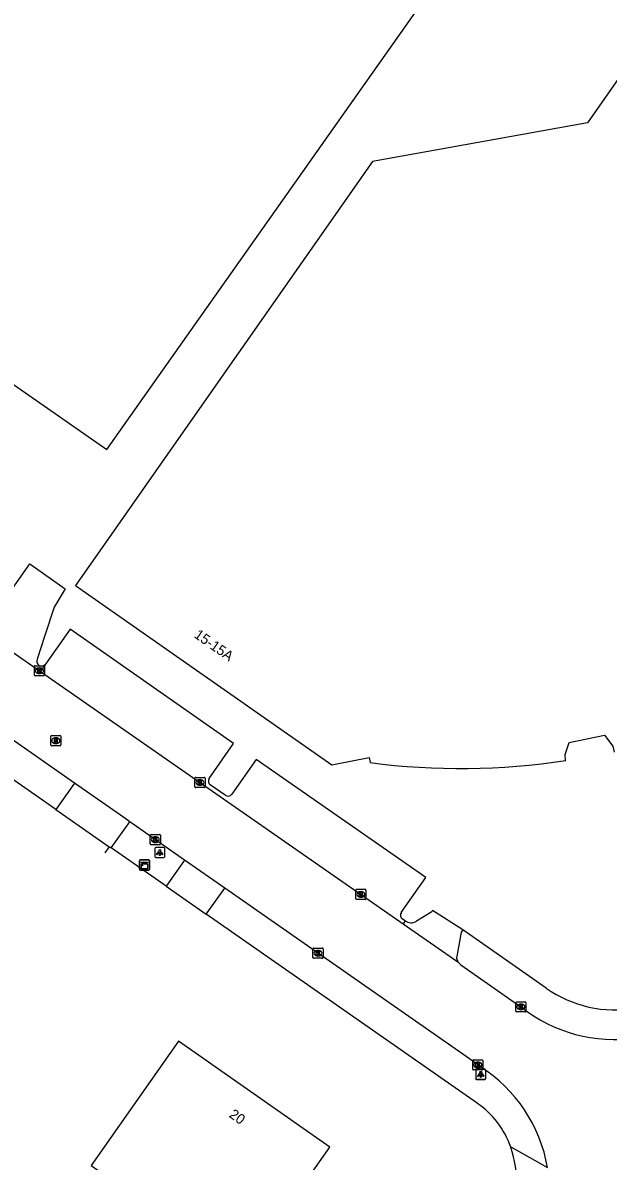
# Model space of a CAD drawing. Extents: x 155018 to 156648, y 383980 to 385733.
# Drawn here: x 155376.9 to 155434.7, y 385021.9 to 385134.4 of the extents above; entities that cross this region are included whole.
import ezdxf

# ---------------------------------------------------------------- set-up
doc = ezdxf.new("R2010")
doc.units = 0
for name, color, linetype in [('IMGEO_Hek', 7, 'Continuous'), ('IMGEO_Kast', 7, 'Continuous'), ('IMGEO_Kolk', 7, 'Continuous'), ('IMGEO_Lichtpunt', 7, 'Continuous'), ('IMGEO_Pand', 7, 'Continuous'), ('IMGEO_Pand_nummerreeks', 7, 'Continuous'), ('IMGEO_Parkeervlak_open', 7, 'Continuous'), ('IMGEO_Rijbaan_lokaal_gesloten', 7, 'Continuous'), ('IMGEO_Rijbaan_lokaal_open', 7, 'Continuous'), ('IMGEO_Rioolput', 7, 'Continuous'), ('IMGEO_Voetpad_open', 7, 'Continuous')]:
    doc.layers.add(name, color=color, linetype=linetype)

msp = doc.modelspace()

# ---------------------------------------------------------------- linework, layer by layer
at = {"layer": 'IMGEO_Hek'}
msp.add_lwpolyline([(155385.4, 385052.96), (155384.98, 385052.36)], dxfattribs=at)
at = {"layer": 'IMGEO_Kast'}
for p, q in [((155388.4, 385050.73), (155388.4, 385051.57)), ((155388.4, 385051.57), (155388.4, 385050.73)), ((155388.47, 385051.65), (155389.31, 385051.65)), ((155389.31, 385051.65), (155388.47, 385051.65)), ((155389.39, 385051.58), (155389.39, 385050.74)), ((155389.39, 385050.74), (155389.39, 385051.58)), ((155389.32, 385050.65), (155388.48, 385050.65)), ((155388.48, 385050.65), (155389.32, 385050.65))]:
    msp.add_line(p, q, dxfattribs=at)
for points in [[(155388.59, 385051.44), (155389.19, 385051.44), (155389.19, 385051.36), (155388.59, 385051.36), (155388.59, 385051.44)], [(155388.59, 385051.27), (155389.19, 385051.27), (155389.19, 385050.78), (155388.59, 385050.78), (155388.59, 385051.27)]]:
    msp.add_lwpolyline(points, dxfattribs=at)
msp.add_circle((155388.67, 385051.12), 0.0377, dxfattribs=at)
for centre, start, end in [((155388.47, 385051.57), 92.4484, 184.2845), ((155388.47, 385051.57), 92.4484, 184.2845), ((155389.32, 385051.57), 2.4484, 94.2845), ((155389.32, 385051.57), 2.4484, 94.2845), ((155388.47, 385050.73), 182.4484, 274.2845), ((155388.47, 385050.73), 182.4484, 274.2845), ((155389.32, 385050.73), 272.4484, 4.2845), ((155389.32, 385050.73), 272.4484, 4.2845)]:
    msp.add_arc(centre, 0.0779, start, end, dxfattribs=at)
at = {"layer": 'IMGEO_Kolk'}
for p, q in [((155378.02, 385069.92), (155378.02, 385070.77)), ((155378.09, 385070.85), (155378.94, 385070.85)), ((155378.53, 385070.07), (155378.5, 385070.07)), ((155378.51, 385070.63), (155378.53, 385070.63)), ((155379.02, 385070.77), (155379.02, 385069.92)), ((155378.94, 385069.85), (155378.09, 385069.85)), ((155393.96, 385059.81), (155394.81, 385059.81)), ((155393.88, 385058.88), (155393.88, 385059.73)), ((155394.81, 385058.81), (155393.96, 385058.81)), ((155394.37, 385059.59), (155394.4, 385059.59)), ((155394.39, 385059.03), (155394.37, 385059.03)), ((155394.88, 385059.73), (155394.88, 385058.88)), ((155389.54, 385054.16), (155390.39, 385054.16)), ((155389.46, 385053.24), (155389.46, 385054.09)), ((155390.39, 385053.16), (155389.54, 385053.16)), ((155389.95, 385053.94), (155389.98, 385053.94)), ((155389.97, 385053.38), (155389.95, 385053.38)), ((155390.46, 385054.09), (155390.46, 385053.24)), ((155409.78, 385047.82), (155409.78, 385048.67)), ((155409.85, 385048.75), (155410.71, 385048.75)), ((155410.27, 385048.52), (155410.29, 385048.52)), ((155410.78, 385048.67), (155410.78, 385047.82)), ((155410.71, 385047.74), (155409.85, 385047.74)), ((155410.29, 385047.97), (155410.26, 385047.97)), ((155405.61, 385042.93), (155406.46, 385042.93)), ((155405.53, 385042.01), (155405.53, 385042.86)), ((155406.46, 385041.93), (155405.61, 385041.93)), ((155406.02, 385042.71), (155406.05, 385042.71)), ((155406.04, 385042.15), (155406.02, 385042.15)), ((155406.54, 385042.86), (155406.54, 385042.01)), ((155425.59, 385036.7), (155425.59, 385037.55)), ((155425.66, 385037.63), (155426.51, 385037.63)), ((155426.08, 385037.41), (155426.1, 385037.41)), ((155426.59, 385037.55), (155426.59, 385036.7)), ((155426.51, 385036.63), (155425.66, 385036.63)), ((155426.1, 385036.85), (155426.07, 385036.85)), ((155421.33, 385030.97), (155421.33, 385031.82)), ((155421.4, 385031.89), (155422.26, 385031.89)), ((155421.82, 385031.67), (155421.84, 385031.67)), ((155422.33, 385031.82), (155422.33, 385030.97)), ((155422.26, 385030.89), (155421.4, 385030.89)), ((155421.84, 385031.11), (155421.81, 385031.11))]:
    msp.add_line(p, q, dxfattribs=at)
for points in [[(155378.02, 385069.92), (155378.02, 385070.77)], [(155378.09, 385070.85), (155378.94, 385070.85)], [(155378.34, 385070.55), (155378.46, 385070.55), (155378.46, 385070.39), (155378.59, 385070.55), (155378.76, 385070.55), (155378.61, 385070.4), (155378.76, 385070.15), (155378.61, 385070.15), (155378.53, 385070.31), (155378.46, 385070.24), (155378.46, 385070.15), (155378.34, 385070.15), (155378.34, 385070.55)], [(155379.02, 385070.77), (155379.02, 385069.92)], [(155378.94, 385069.85), (155378.09, 385069.85)], [(155393.96, 385059.81), (155394.81, 385059.81)], [(155393.88, 385058.88), (155393.88, 385059.73)], [(155394.81, 385058.81), (155393.96, 385058.81)], [(155394.2, 385059.51), (155394.33, 385059.51), (155394.33, 385059.36), (155394.46, 385059.51), (155394.62, 385059.51), (155394.47, 385059.36), (155394.63, 385059.11), (155394.47, 385059.11), (155394.39, 385059.27), (155394.33, 385059.2), (155394.33, 385059.11), (155394.2, 385059.11), (155394.2, 385059.51)], [(155394.88, 385059.73), (155394.88, 385058.88)], [(155389.54, 385054.16), (155390.39, 385054.16)], [(155389.46, 385053.24), (155389.46, 385054.09)], [(155390.39, 385053.16), (155389.54, 385053.16)], [(155389.78, 385053.86), (155389.91, 385053.86), (155389.91, 385053.71), (155390.04, 385053.86), (155390.2, 385053.86), (155390.05, 385053.71), (155390.21, 385053.46), (155390.05, 385053.46), (155389.97, 385053.63), (155389.91, 385053.56), (155389.91, 385053.46), (155389.78, 385053.46), (155389.78, 385053.86)], [(155390.46, 385054.09), (155390.46, 385053.24)], [(155409.78, 385047.82), (155409.78, 385048.67)], [(155409.85, 385048.75), (155410.71, 385048.75)], [(155410.78, 385048.67), (155410.78, 385047.82)], [(155410.71, 385047.74), (155409.85, 385047.74)], [(155410.1, 385048.44), (155410.22, 385048.44), (155410.22, 385048.29), (155410.35, 385048.44), (155410.52, 385048.44), (155410.37, 385048.29), (155410.52, 385048.04), (155410.37, 385048.04), (155410.29, 385048.21), (155410.22, 385048.14), (155410.22, 385048.04), (155410.1, 385048.04), (155410.1, 385048.44)], [(155405.61, 385042.93), (155406.46, 385042.93)], [(155405.53, 385042.01), (155405.53, 385042.86)], [(155406.46, 385041.93), (155405.61, 385041.93)], [(155405.85, 385042.63), (155405.98, 385042.63), (155405.98, 385042.48), (155406.11, 385042.63), (155406.27, 385042.63), (155406.13, 385042.48), (155406.28, 385042.23), (155406.13, 385042.23), (155406.04, 385042.4), (155405.98, 385042.33), (155405.98, 385042.23), (155405.85, 385042.23), (155405.85, 385042.63)], [(155406.54, 385042.86), (155406.54, 385042.01)], [(155425.59, 385036.7), (155425.59, 385037.55)], [(155425.66, 385037.63), (155426.51, 385037.63)], [(155425.91, 385037.33), (155426.03, 385037.33), (155426.03, 385037.18), (155426.16, 385037.33), (155426.33, 385037.33), (155426.18, 385037.18), (155426.33, 385036.93), (155426.18, 385036.93), (155426.1, 385037.09), (155426.03, 385037.02), (155426.03, 385036.93), (155425.91, 385036.93), (155425.91, 385037.33)], [(155426.59, 385037.55), (155426.59, 385036.7)], [(155426.51, 385036.63), (155425.66, 385036.63)], [(155421.33, 385030.97), (155421.33, 385031.82)], [(155421.4, 385031.89), (155422.26, 385031.89)], [(155422.33, 385031.82), (155422.33, 385030.97)], [(155422.26, 385030.89), (155421.4, 385030.89)], [(155421.65, 385031.59), (155421.77, 385031.59), (155421.77, 385031.44), (155421.9, 385031.59), (155422.07, 385031.59), (155421.92, 385031.44), (155422.07, 385031.19), (155421.92, 385031.19), (155421.84, 385031.36), (155421.77, 385031.29), (155421.77, 385031.19), (155421.65, 385031.19), (155421.65, 385031.59)]]:
    msp.add_lwpolyline(points, dxfattribs=at)
for centre, start, end in [((155378.09, 385070.77), 91.552, 178.448), ((155378.09, 385070.77), 91.552, 178.448), ((155378.09, 385069.92), 181.552, 268.448), ((155378.09, 385069.92), 181.552, 268.448), ((155378.94, 385070.77), 1.552, 88.448), ((155378.94, 385070.77), 1.552, 88.448), ((155378.94, 385069.92), 271.552, 358.448), ((155378.94, 385069.92), 271.552, 358.448), ((155393.96, 385059.73), 91.552, 178.448), ((155393.96, 385059.73), 91.552, 178.448), ((155394.81, 385059.73), 1.552, 88.448), ((155394.81, 385059.73), 1.552, 88.448), ((155393.96, 385058.88), 181.552, 268.448), ((155393.96, 385058.88), 181.552, 268.448), ((155394.81, 385058.88), 271.552, 358.448), ((155394.81, 385058.88), 271.552, 358.448), ((155389.54, 385054.09), 91.552, 178.448), ((155389.54, 385054.09), 91.552, 178.448), ((155390.39, 385054.09), 1.552, 88.448), ((155390.39, 385054.09), 1.552, 88.448), ((155389.54, 385053.24), 181.552, 268.448), ((155389.54, 385053.24), 181.552, 268.448), ((155390.39, 385053.24), 271.552, 358.448), ((155390.39, 385053.24), 271.552, 358.448), ((155409.86, 385048.67), 91.552, 178.448), ((155409.86, 385048.67), 91.552, 178.448), ((155410.7, 385048.67), 1.552, 88.448), ((155410.7, 385048.67), 1.552, 88.448), ((155409.86, 385047.82), 181.552, 268.448), ((155409.86, 385047.82), 181.552, 268.448), ((155410.7, 385047.82), 271.552, 358.448), ((155410.7, 385047.82), 271.552, 358.448), ((155405.61, 385042.86), 91.552, 178.448), ((155405.61, 385042.86), 91.552, 178.448), ((155406.46, 385042.86), 1.552, 88.448), ((155406.46, 385042.86), 1.552, 88.448), ((155405.61, 385042.01), 181.552, 268.448), ((155405.61, 385042.01), 181.552, 268.448), ((155406.46, 385042.01), 271.552, 358.448), ((155406.46, 385042.01), 271.552, 358.448), ((155425.66, 385037.55), 91.552, 178.448), ((155425.66, 385037.55), 91.552, 178.448), ((155426.51, 385037.55), 1.552, 88.448), ((155426.51, 385037.55), 1.552, 88.448), ((155425.66, 385036.7), 181.552, 268.448), ((155425.66, 385036.7), 181.552, 268.448), ((155426.51, 385036.7), 271.552, 358.448), ((155426.51, 385036.7), 271.552, 358.448), ((155421.4, 385031.82), 91.552, 178.448), ((155421.4, 385031.82), 91.552, 178.448), ((155422.25, 385031.82), 1.552, 88.448), ((155422.25, 385031.82), 1.552, 88.448), ((155421.4, 385030.97), 181.552, 268.448), ((155421.4, 385030.97), 181.552, 268.448), ((155422.25, 385030.97), 271.552, 358.448), ((155422.25, 385030.97), 271.552, 358.448)]:
    msp.add_arc(centre, 0.0765, start, end, dxfattribs=at)
for centre, major_axis, ratio, start_param, end_param in [((155378.5, 385070.35), (-0.387, 0.002), 0.722429, 4.712389, 7.853982), ((155378.53, 385070.35), (-0.39, 0.002), 0.717154, 1.570796, 4.712389), ((155394.37, 385059.31), (-0.387, 0.002), 0.722429, 4.712389, 7.853982), ((155394.39, 385059.31), (-0.39, 0.002), 0.717154, 1.570796, 4.712389), ((155389.95, 385053.66), (-0.387, 0.002), 0.722429, 4.712389, 7.853982), ((155389.97, 385053.66), (-0.39, 0.002), 0.717154, 1.570796, 4.712389), ((155410.27, 385048.24), (-0.387, 0.002), 0.722429, 4.712389, 7.853982), ((155410.29, 385048.24), (-0.39, 0.002), 0.717154, 1.570796, 4.712389), ((155406.02, 385042.43), (-0.387, 0.002), 0.722429, 4.712389, 7.853982), ((155406.05, 385042.43), (-0.39, 0.002), 0.717154, 1.570796, 4.712389), ((155426.07, 385037.13), (-0.387, 0.002), 0.722429, 4.712389, 7.853982), ((155426.1, 385037.13), (-0.39, 0.002), 0.717154, 1.570796, 4.712389), ((155421.82, 385031.39), (-0.387, 0.002), 0.722429, 4.712389, 7.853982), ((155421.84, 385031.39), (-0.39, 0.002), 0.717154, 1.570796, 4.712389)]:
    msp.add_ellipse(centre, major_axis=major_axis, ratio=ratio, start_param=start_param, end_param=end_param, dxfattribs=at)
at = {"layer": 'IMGEO_Lichtpunt'}
for p, q in [((155389.9, 385052.78), (155389.9, 385051.98)), ((155389.9, 385052.78), (155389.9, 385051.98)), ((155390.8, 385052.88), (155390, 385052.88)), ((155390.8, 385052.88), (155390, 385052.88)), ((155390, 385051.88), (155390.8, 385051.88)), ((155390, 385051.88), (155390.8, 385051.88)), ((155390.9, 385051.98), (155390.9, 385052.78)), ((155390.9, 385051.98), (155390.9, 385052.78)), ((155421.62, 385030.86), (155421.62, 385030.05)), ((155421.62, 385030.86), (155421.62, 385030.05)), ((155421.63, 385030.88), (155421.63, 385030.07)), ((155421.63, 385030.88), (155421.63, 385030.07)), ((155422.52, 385030.95), (155421.71, 385030.95)), ((155422.52, 385030.95), (155421.71, 385030.95)), ((155422.53, 385030.97), (155421.72, 385030.97)), ((155422.53, 385030.97), (155421.72, 385030.97)), ((155422.62, 385030.05), (155422.62, 385030.86)), ((155422.62, 385030.05), (155422.62, 385030.86)), ((155422.63, 385030.07), (155422.63, 385030.88)), ((155422.63, 385030.07), (155422.63, 385030.88)), ((155421.71, 385029.95), (155422.52, 385029.95)), ((155421.71, 385029.95), (155422.52, 385029.95)), ((155421.72, 385029.98), (155422.53, 385029.98)), ((155421.72, 385029.98), (155422.53, 385029.98))]:
    msp.add_line(p, q, dxfattribs=at)
for points in [[(155390.28, 385052.45), (155390.31, 385052.42), (155390.13, 385052.16), (155390.09, 385052.18), (155390.28, 385052.45)], [(155390.38, 385052.4), (155390.43, 385052.4), (155390.43, 385052.08), (155390.38, 385052.08), (155390.38, 385052.4)], [(155390.49, 385052.42), (155390.53, 385052.45), (155390.71, 385052.18), (155390.67, 385052.16), (155390.49, 385052.42)], [(155421.99, 385030.52), (155422.03, 385030.49), (155421.85, 385030.23), (155421.81, 385030.26), (155421.99, 385030.52)], [(155422, 385030.54), (155422.04, 385030.51), (155421.85, 385030.25), (155421.82, 385030.28), (155422, 385030.54)], [(155422.1, 385030.49), (155422.15, 385030.49), (155422.15, 385030.17), (155422.1, 385030.17), (155422.1, 385030.49)], [(155422.21, 385030.51), (155422.25, 385030.54), (155422.44, 385030.28), (155422.4, 385030.25), (155422.21, 385030.51)], [(155422.21, 385030.49), (155422.24, 385030.52), (155422.43, 385030.26), (155422.39, 385030.23), (155422.21, 385030.49)], [(155422.1, 385030.47), (155422.14, 385030.47), (155422.14, 385030.15), (155422.1, 385030.15), (155422.1, 385030.47)]]:
    msp.add_lwpolyline(points, dxfattribs=at)
for centre in [(155390.4, 385052.58), (155422.12, 385030.65), (155422.13, 385030.68)]:
    msp.add_circle(centre, 0.0994, dxfattribs=at)
for centre, start, end in [((155390, 385052.78), 90, 180), ((155390, 385052.78), 90, 180), ((155390, 385051.98), 180, 270), ((155390, 385051.98), 180, 270), ((155390.8, 385052.78), 0, 90), ((155390.8, 385052.78), 0, 90), ((155390.8, 385051.98), 270, 0), ((155390.8, 385051.98), 270, 360), ((155421.71, 385030.86), 90, 180), ((155421.71, 385030.86), 90, 180), ((155421.72, 385030.88), 90, 180), ((155421.72, 385030.88), 90, 180), ((155422.52, 385030.86), 0, 90), ((155422.52, 385030.86), 0, 90), ((155422.53, 385030.88), 0, 90), ((155422.53, 385030.88), 0, 90), ((155421.71, 385030.05), 180, 270), ((155421.71, 385030.05), 180, 270), ((155421.72, 385030.07), 180, 270), ((155421.72, 385030.07), 180, 270), ((155422.52, 385030.05), 270, 0), ((155422.52, 385030.05), 270, 360), ((155422.53, 385030.07), 270, 0), ((155422.53, 385030.07), 270, 360)]:
    msp.add_arc(centre, 0.0946, start, end, dxfattribs=at)
at = {"layer": 'IMGEO_Pand'}
for points in [[(155442.01, 385172.85), (155443.27, 385174.66), (155413.9, 385195.2), (155370.63, 385133.35), (155367.77, 385129.25), (155364.49, 385131.54), (155359.43, 385135.08), (155348.62, 385119.63), (155349.5, 385119.02), (155349.89, 385116.96), (155349.27, 385116.07), (155368.07, 385102.91), (155368.63, 385103.71), (155385.16, 385092.22), (155424.54, 385148.03), (155428.3, 385153.34)], [(155453.5, 385068.76), (155453.46, 385069.27), (155457.22, 385069.83), (155474.93, 385095.15), (155466.59, 385100.98), (155471.9, 385108.58), (155467.8, 385111.44), (155438.05, 385132.17), (155432.67, 385124.51), (155411.43, 385120.68), (155384.95, 385082.87), (155382.08, 385078.78), (155407.39, 385061.04), (155411.11, 385061.77), (155411.2, 385061.27)], [(155430.51, 385061.49), (155430.45, 385062.06), (155430.85, 385063.25), (155434.35, 385063.97), (155435.16, 385062.9), (155435.29, 385062.31)], [(155392.24, 385033.74), (155383.64, 385021.45), (155391.17, 385016.18), (155383.58, 385005.33), (155384.29, 385004.83), (155382.52, 385002.29), (155370.02, 385011.04), (155362.29, 385000), (155351.35, 384984.37), (155341.94, 384971), (155365.99, 384954.13), (155375.42, 384967.49), (155394.1, 384994.2), (155393.37, 384994.69), (155395.14, 384997.23), (155395.89, 384996.73), (155398.18, 385000), (155408.66, 385014.97), (155405.76, 385017.03), (155407.12, 385018.99), (155405.17, 385020.37), (155407.2, 385023.27), (155392.24, 385033.74)]]:
    msp.add_lwpolyline(points, dxfattribs=at)
msp.add_arc((155420.09, 385128.88), 68.19, 262.5127, 278.7928, dxfattribs=at)
at = {"layer": 'IMGEO_Parkeervlak_open'}
for points in [[(155395.29, 385059.71), (155397.68, 385063.16), (155381.55, 385074.47), (155379.11, 385071)], [(155414.27, 385046.44), (155416.71, 385049.91), (155399.93, 385061.59), (155397.52, 385058.14)], [(155396.88, 385058.05), (155395.38, 385059.08)], [(155414.64, 385045.64), (155414.38, 385045.81)]]:
    msp.add_lwpolyline(points, dxfattribs=at)
for centre, radius, start, end in [((155395.67, 385059.44), 0.467, 145.0809, 231.9365), ((155397.15, 385058.44), 0.48, 235.7591, 321.0496), ((155414.64, 385046.18), 0.45, 144.5673, 234.7412)]:
    msp.add_arc(centre, radius, start, end, dxfattribs=at)
at = {"layer": 'IMGEO_Rijbaan_lokaal_gesloten'}
for points in [[(155381.97, 385059.23), (155343.17, 385086.38)], [(155371.07, 385075.54), (155373.16, 385074.07), (155378.61, 385070.28)], [(155378.61, 385070.28), (155414.44, 385045.35)], [(155387.45, 385055.41), (155386.95, 385055.78), (155381.97, 385059.23)], [(155392.86, 385051.63), (155387.45, 385055.41)], [(155396.82, 385048.86), (155392.86, 385051.63)], [(155422.08, 385031.23), (155396.82, 385048.86)], [(155414.44, 385045.35), (155419.86, 385041.58)], [(155419.86, 385041.58), (155420.14, 385041.29), (155426.08, 385037.13)]]:
    msp.add_lwpolyline(points, dxfattribs=at)
for centre, radius, start, end in [((155435.31, 385048.68), 14.78, 231.3745, 278.4802), ((155414.09, 385018.7), 14.85, 9.924, 57.4853)]:
    msp.add_arc(centre, radius, start, end, dxfattribs=at)
at = {"layer": 'IMGEO_Rijbaan_lokaal_open'}
for points in [[(155374.69, 385076.84), (155377.55, 385080.91), (155381.07, 385078.44), (155379.97, 385076.65), (155379.05, 385073.83), (155378.3, 385071.51)], [(155379.11, 385071), (155378.61, 385070.28)], [(155381.97, 385059.23), (155380.15, 385056.63)], [(155380.15, 385056.63), (155385.4, 385052.96), (155385.59, 385052.84)], [(155385.59, 385052.84), (155387.45, 385055.41)], [(155392.86, 385051.63), (155391.03, 385049.05)], [(155391.03, 385049.05), (155395, 385046.28)], [(155395, 385046.28), (155396.82, 385048.86)], [(155420.34, 385044.73), (155417.36, 385046.64), (155417.28, 385046.53), (155415.76, 385045.6)], [(155414.64, 385045.64), (155414.44, 385045.35)], [(155420.34, 385044.73), (155420.18, 385044.51), (155419.73, 385041.95), (155419.86, 385041.58)]]:
    msp.add_lwpolyline(points, dxfattribs=at)
for centre, radius, start, end in [((155378.73, 385071.29), 0.481, 152.7207, 240.842), ((155378.73, 385071.29), 0.475, 240.5056, 323.6459), ((155415.23, 385046.4), 0.959, 232.6746, 303.6203)]:
    msp.add_arc(centre, radius, start, end, dxfattribs=at)
at = {"layer": 'IMGEO_Rioolput'}
for p, q in [((155379.64, 385063.02), (155379.64, 385063.87)), ((155379.71, 385063.94), (155380.56, 385063.94)), ((155380.15, 385063.16), (155380.12, 385063.16)), ((155380.13, 385063.72), (155380.15, 385063.72)), ((155380.64, 385063.87), (155380.64, 385063.02)), ((155380.56, 385062.94), (155379.71, 385062.94))]:
    msp.add_line(p, q, dxfattribs=at)
for points in [[(155379.64, 385063.02), (155379.64, 385063.87)], [(155379.71, 385063.94), (155380.56, 385063.94)], [(155380.23, 385063.64), (155379.97, 385063.64), (155379.97, 385063.24)], [(155379.97, 385063.24), (155380.1, 385063.24), (155380.1, 385063.41), (155380.11, 385063.41)], [(155380.15, 385063.56), (155380.1, 385063.56), (155380.1, 385063.48)], [(155380.1, 385063.48), (155380.15, 385063.48)], [(155380.16, 385063.38), (155380.23, 385063.24), (155380.37, 385063.24), (155380.3, 385063.37)], [(155380.64, 385063.87), (155380.64, 385063.02)], [(155380.56, 385062.94), (155379.71, 385062.94)]]:
    msp.add_lwpolyline(points, dxfattribs=at)
for centre, radius, start, end in [((155379.71, 385063.87), 0.0765, 91.552, 178.448), ((155379.71, 385063.87), 0.0765, 91.552, 178.448), ((155380.11, 385063.35), 0.0533, 26.0293, 88.6989), ((155380.16, 385063.47), 0.0964, 77.0061, 93.1865), ((155380.13, 385063.67), 0.19, 274.7715, 282.9687), ((155380.17, 385063.52), 0.0378, 276.6634, 79.6772), ((155380.23, 385063.53), 0.109, 350.3612, 89.416), ((155380.22, 385063.53), 0.112, 277.5842, 350.9817), ((155380.21, 385063.32), 0.108, 29.5134, 73.7905), ((155380.56, 385063.87), 0.0765, 1.552, 88.448), ((155380.56, 385063.87), 0.0765, 1.552, 88.448), ((155379.71, 385063.02), 0.0765, 181.552, 268.448), ((155379.71, 385063.02), 0.0765, 181.552, 268.448), ((155380.56, 385063.02), 0.0765, 271.552, 358.448), ((155380.56, 385063.02), 0.0765, 271.552, 358.448)]:
    msp.add_arc(centre, radius, start, end, dxfattribs=at)
for centre, major_axis, ratio, start_param, end_param in [((155380.12, 385063.44), (-0.387, 0.002), 0.722429, 4.712389, 7.853982), ((155380.15, 385063.44), (-0.39, 0.002), 0.717154, 1.570796, 4.712389)]:
    msp.add_ellipse(centre, major_axis=major_axis, ratio=ratio, start_param=start_param, end_param=end_param, dxfattribs=at)
at = {"layer": 'IMGEO_Voetpad_open'}
for points in [[(155380.15, 385056.63), (155341.35, 385083.76)], [(155391.03, 385049.05), (155385.59, 385052.84)], [(155421.75, 385027.62), (155395, 385046.28)], [(155428.58, 385038.98), (155420.34, 385044.73)], [(155425.08, 385023.28), (155428.72, 385021.26)]]:
    msp.add_lwpolyline(points, dxfattribs=at)
for centre, radius, start, end in [((155435.35, 385048.55), 11.72, 234.7369, 325.6532), ((155416.88, 385020.44), 8.67, 37.457, 55.8479), ((155416.87, 385020.42), 8.69, 19.1756, 37.524), ((155409.51, 385018.58), 16.27, 348.9398, 16.7616)]:
    msp.add_arc(centre, radius, start, end, dxfattribs=at)

# ---------------------------------------------------------------- texts
at = {"layer": 'IMGEO_Pand_nummerreeks'}
for s, rotation, p in [('15-15A', 324.973, (155393.71, 385073.71)), ('20', 325.0131, (155397.17, 385026.29))]:
    msp.add_text(s, height=1, rotation=rotation, dxfattribs=at).set_placement(p)

doc.saveas('drawing.dxf')
